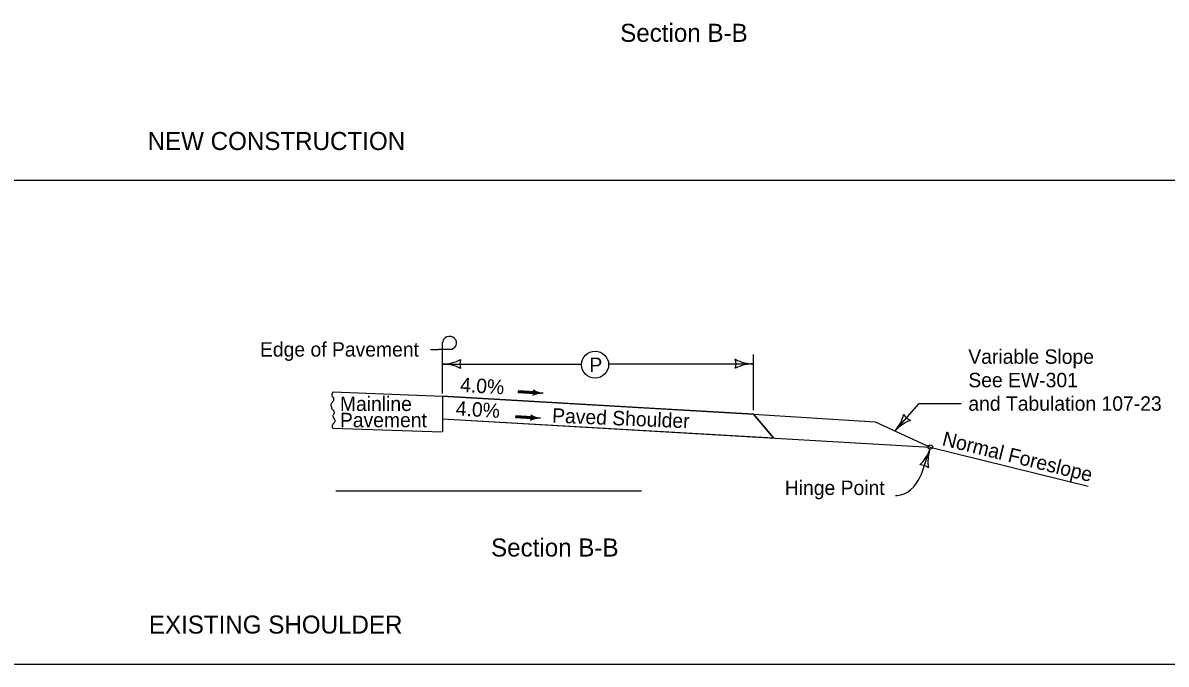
# Model space of a CAD drawing. Extents: x -1548 to 1548, y -960 to 993.
# Drawn here: x -756 to 510, y -960 to -249 of the extents above; entities that cross this region are included whole.
import ezdxf

# ---------------------------------------------------------------- set-up
doc = ezdxf.new("R2010")
doc.units = 0
for name, color, linetype in [('dsnStdBorder', 7, 'Continuous'), ('dsnStdDimension', 7, 'Continuous'), ('dsnStdLabel', 7, 'Continuous'), ('dsnStdLineWork', 7, 'Continuous'), ('dsnStdShading', 7, 'Continuous'), ('Level 4', 7, 'Continuous')]:
    doc.layers.add(name, color=color, linetype=linetype)

msp = doc.modelspace()

# ---------------------------------------------------------------- linework, layer by layer
at = {"layer": 'dsnStdBorder'}
msp.add_line((-1547.8, -960), (1547.8, -960), dxfattribs=at)
at = {"layer": 'dsnStdDimension'}
for p, q in [((53, -678.4), (53, -616.7)), ((-291.3, -627.3), (-137.4, -627.3)), ((-107.5, -627.1), (53, -627.1))]:
    msp.add_line(p, q, dxfattribs=at)
msp.add_circle((-122.4, -628.1), 15, dxfattribs=at)
for centre, radius, start, end in [((-291.3, -584.8), 42.5, 270, 298.0725), ((-291.3, -669.8), 42.5, 61.9275, 90), ((-255.7, -627.3), 16.4, 162.2666, 197.7334), ((17.3, -627.1), 16.4, 342.2666, 17.7333), ((53, -584.6), 42.5, 241.9275, 270), ((53, -669.6), 42.5, 90, 118.0725)]:
    msp.add_arc(centre, radius, start, end, dxfattribs=at)
at = {"layer": 'dsnStdLabel'}
for p, q in [((-291.3, -623.9), (-291.3, -603.1)), ((-304.7, -611.1), (-296, -611.1)), ((-283.5, -611.1), (-296, -611.1)), ((-291.3, -659.9), (-291.3, -623.9)), ((-189.4, -659.1), (-207.6, -658)), ((-189.3, -658.1), (-189.3, -658.1)), ((-189.5, -660), (-189.5, -660)), ((209.9, -701.5), (236.5, -671.1)), ((236.5, -671.1), (282.9, -671.1)), ((-192.2, -686.7), (-210.4, -685.7)), ((-192.3, -687.7), (-192.3, -687.7)), ((-192.2, -685.7), (-192.2, -685.7)), ((239.1, -749.3), (248.5, -721.7))]:
    msp.add_line(p, q, dxfattribs=at)
for points in [[(-189.3, -658.2), (-207.5, -657.1), (-207.6, -659), (-189.5, -660), (-189.4, -658.4), (-207.3, -657.3), (-207.3, -658.8), (-189.8, -659.8), (-189.7, -658.7), (-207, -657.6), (-207.1, -658.6), (-190.1, -659.6), (-190, -658.9), (-206.8, -657.8), (-206.9, -658.4), (-190.3, -659.3)], [(-189.7, -656.9), (-189, -658.1), (-189.1, -659.7), (-189.8, -661.1), (-187.1, -660.2), (-183.9, -659.6), (-183, -659.5), (-185.2, -658.9), (-188.4, -657.7), (-189.4, -657.2), (-189.3, -660.7), (-184.3, -659.4), (-188.9, -657.9), (-188.9, -660.3), (-185.5, -659.4), (-188.5, -658.5), (-188.8, -659.9), (-186.6, -659.4), (-188.2, -658.9), (-188.3, -659.5), (-187.5, -659.4)], [(-192.1, -685.8), (-210.3, -684.7), (-210.4, -686.6), (-192.3, -687.7), (-192.2, -686), (-210.1, -685), (-210.1, -686.5), (-192.7, -687.4), (-192.5, -686.3), (-209.9, -685.2), (-209.9, -686.2), (-192.9, -687.2), (-192.8, -686.5), (-209.7, -685.4), (-209.7, -686), (-193.1, -686.9)], [(-192.5, -684.5), (-191.9, -685.7), (-191.9, -687.3), (-192.6, -688.7), (-189.9, -687.9), (-186.7, -687.2), (-185.8, -687.1), (-188, -686.5), (-191.3, -685.3), (-192.2, -684.8), (-192.1, -688.3), (-187.1, -687.1), (-191.8, -685.5), (-191.8, -687.9), (-188.4, -687), (-191.4, -686.1), (-191.6, -687.5), (-189.4, -687), (-191, -686.5), (-191.2, -687.2), (-190.4, -687)]]:
    msp.add_lwpolyline(points, dxfattribs=at)
for centre, radius, start, end in [((177.9, -673.5), 42.5, 318.8454, 346.9178), ((233.3, -674.7), 16.4, 211.112, 246.5787), ((241.9, -729.5), 42.5, 110.7729, 138.8454), ((208.3, -707.9), 42.5, 312.9788, 341.0513), ((288.7, -735.5), 42.5, 161.0513, 189.1238), ((236.9, -755.4), 16.4, 53.3179, 88.7846)]:
    msp.add_arc(centre, radius, start, end, dxfattribs=at)
for centre, major_axis, ratio, start_param, end_param in [((-283.5, -603.9), (-7.81, 0), 0.913811, 1.570796, 6.283185), ((-193.1, -658.9), (3.88, 0), 0.913811, 5.202895, 7.237436), ((-178.1, -639.5), (-22.2, 0), 0.913811, 0.954258, 1.478381), ((-180.8, -679.9), (22.2, 0), 0.913811, 1.537172, 2.061295), ((-195.9, -686.5), (3.88, 0), 0.913811, 5.202895, 7.237436), ((-180.9, -667.1), (-22.2, 0), 0.913811, 0.954258, 1.478381), ((-183.7, -707.5), (22.2, 0), 0.913811, 1.537172, 2.061295), ((212, -711.4), (0, 61.5), 0.559383, 3.141593, 4.048985)]:
    msp.add_ellipse(centre, major_axis=major_axis, ratio=ratio, start_param=start_param, end_param=end_param, dxfattribs=at)
at = {"layer": 'dsnStdLineWork'}
for p, q in [((-412.7, -658.1), (-291.3, -663)), ((-291.3, -663), (-291.3, -688.2)), ((-291.3, -663), (53, -683)), ((52.5, -682.8), (52.5, -682.8)), ((53, -682.9), (187.7, -691.3)), ((53, -683), (75.2, -709.3)), ((-291.3, -688.2), (248.8, -719.3)), ((-291.3, -688.2), (-291.3, -702.6)), ((187.7, -691.3), (248.8, -719.3)), ((-413.2, -698.6), (-291.6, -702.6)), ((75.2, -709.3), (75.2, -709.3)), ((248.8, -719.3), (423.8, -762.7)), ((-409.4, -767.9), (-70.9, -767.9)), ((210.4, -772.9), (212, -772.9))]:
    msp.add_line(p, q, dxfattribs=at)
msp.add_ellipse((248.8, -719.3), major_axis=(2.58, 0), ratio=0.913811, dxfattribs=at)
for points in [[(-412.7, -658.1), (-413.9, -662.7), (-412.9, -664.2), (-412, -666.5), (-412.6, -668.6), (-414.5, -671), (-415, -672.9), (-414.5, -675.2), (-413.6, -677.5), (-412.6, -678.3), (-411.2, -680.8), (-411.2, -681.6)], [(-411.2, -681.6), (-411.4, -681.9), (-411.6, -682.1), (-412, -682.7), (-412.5, -683.9), (-412.7, -685.1), (-412.6, -685.7), (-412.6, -686), (-412.5, -686.3), (-412.3, -686.7), (-412, -687), (-411.7, -687.4), (-411.4, -687.8), (-411.3, -688.1), (-411.2, -688.4), (-410.9, -688.9), (-410.6, -690.1), (-410.6, -690.2), (-410.6, -690.3), (-410.7, -691.1), (-410.9, -691.6), (-411.2, -692.1), (-411.6, -692.8), (-412.1, -693.3), (-412.7, -693.9), (-412.9, -694.2), (-413.1, -694.5), (-413.3, -695), (-413.5, -695.5), (-413.6, -695.9), (-413.6, -696.2), (-413.6, -696.4), (-413.5, -696.9), (-413.4, -697.5), (-413.3, -698), (-413.1, -698.6)]]:
    msp.add_spline(points, degree=3, dxfattribs=at)
at = {"layer": 'dsnStdShading'}
msp.add_lwpolyline([(-62.9, -676.3), (-62.9, -676.3), (-291.3, -663), (-291.3, -688.2), (75.2, -709.3), (53, -683), (-62.9, -676.3)], dxfattribs=at)
at = {"layer": 'Level 4'}
msp.add_line((607.7, -424), (-1547.8, -424), dxfattribs=at)

# ---------------------------------------------------------------- texts
at = {"layer": 'dsnStdDimension'}
msp.add_text('P', height=16, dxfattribs=at).set_placement((-128.7, -636.2))
at = {"layer": 'dsnStdLabel'}
for s, height, p in [('Section B-B', 20, (-94.6, -270.2)), ('NEW CONSTRUCTION', 20, (-618, -390.1)), ('Edge of Pavement', 16, (-493.5, -619.1)), ('Variable Slope', 16, (291, -627.1)), ('See EW-301', 16, (291, -653.1)), ('Mainline', 16, (-405, -679.4)), ('and Tabulation 107-23', 16, (291, -679.1)), ('Pavement', 16, (-405, -697.4)), ('Hinge Point', 16, (87.7, -772.5)), ('Section B-B', 20, (-237.6, -840.7)), ('EXISTING SHOULDER', 20, (-616.6, -926.1))]:
    msp.add_text(s, height=height, dxfattribs=at).set_placement(p)
for s, rotation, p in [('4.0%', 356.6992, (-272.2, -658.2)), ('4.0%', 356.6992, (-277, -684.3)), ('Paved Shoulder ', 357.5923, (-170.2, -692.2)), ('Normal Foreslope', 346.0988, (261.1, -717.3))]:
    msp.add_text(s, height=16, rotation=rotation, dxfattribs=at).set_placement(p)

doc.saveas('drawing.dxf')
